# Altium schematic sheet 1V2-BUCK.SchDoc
size A2; SheetNumber: 5; SheetTotal: 17
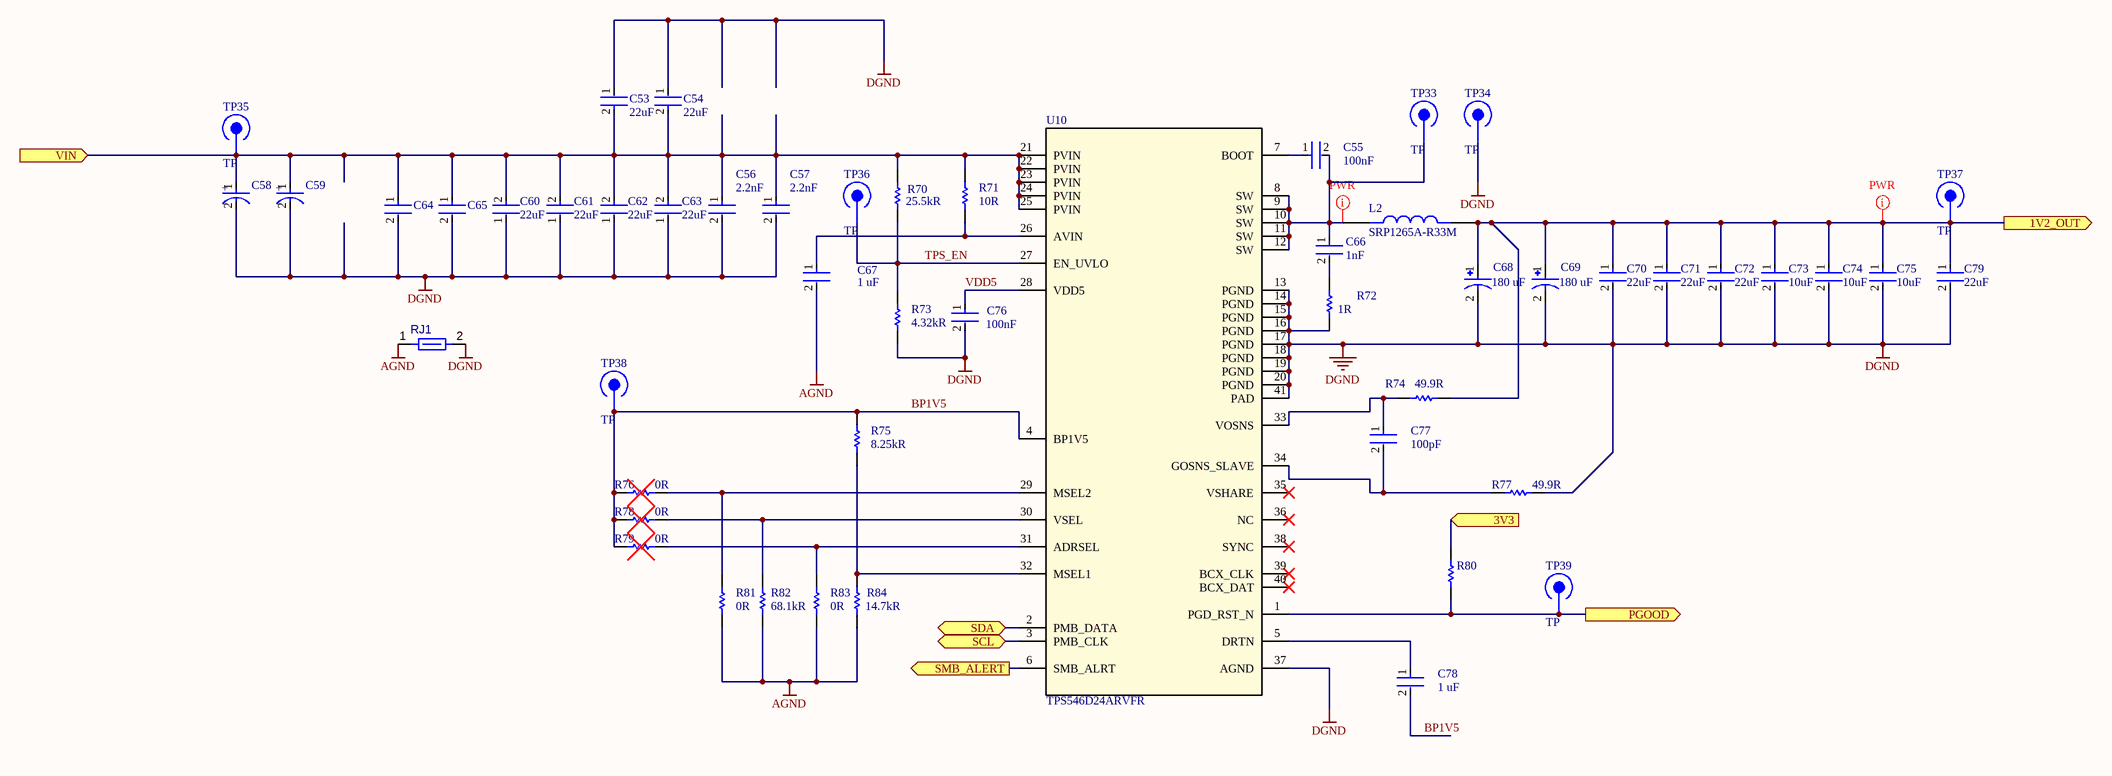
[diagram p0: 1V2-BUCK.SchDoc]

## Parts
C53  Capacitance: 22uF  [FP-GRM31C-0_3-e0_3_0_8-MFG]  (hidden comment: GRM31CC81E226ME11L)
C54  Capacitance: 22uF  [FP-GRM31C-0_3-e0_3_0_8-MFG]  (hidden comment: GRM31CC81E226ME11L)
C55  value 100nF  [FP-CC0402-IPC_B]  (hidden comment: CC0402KRX7R9BB104)
C56  value 2.2nF  [FP-CC0402-MFG]  (hidden comment: CC0402KRX7R8BB222)
C57  value 2.2nF  [FP-CC0402-MFG]  (hidden comment: CC0402KRX7R8BB222)
C58  593D107X9020E2TE3  [593D107X9020E2TE3-Footprint-1]  (value not drawn)
C59  593D107X9020E2TE3  [593D107X9020E2TE3-Footprint-1]  (value not drawn)
C60  Capacitance: 22uF  [FP-GRM31C-0_3-e0_3_0_8-MFG]  (hidden comment: GRM31CC81E226ME11L)
C61  Capacitance: 22uF  [FP-GRM31C-0_3-e0_3_0_8-MFG]  (hidden comment: GRM31CC81E226ME11L)
C62  Capacitance: 22uF  [FP-GRM31C-0_3-e0_3_0_8-MFG]  (hidden comment: GRM31CC81E226ME11L)
C63  Capacitance: 22uF  [FP-GRM31C-0_3-e0_3_0_8-MFG]  (hidden comment: GRM31CC81E226ME11L)
C64  C3216X5R1E476M160AC  [FP-C3216-160-0_2-MFG]  (value not drawn)
C65  C3216X5R1E476M160AC  [FP-C3216-160-0_2-MFG]  (value not drawn)
C66  value 1nF  [FP-CC0805-0_85-MFG]  (hidden comment: CC0805KRX7R9BB102)
C67  value 1 uF  [FP-CC0402-MFG]  (hidden comment: CC0402KRX5R6BB105)
C68  value 180 uF  [EEF-SX0J181ER-Footprint-1]  (hidden comment: EEF-SX0J181ER)
C69  value 180 uF  [EEF-SX0J181ER-Footprint-1]  (hidden comment: EEF-SX0J181ER)
C70  value 22uF  [FP-GRM21B-0_2-e0_2_0_7-MFG]  (hidden comment: GRM21BZ70J226ME44L)
C71  value 22uF  [FP-GRM21B-0_2-e0_2_0_7-MFG]  (hidden comment: GRM21BZ70J226ME44L)
C72  value 22uF  [FP-GRM21B-0_2-e0_2_0_7-MFG]  (hidden comment: GRM21BZ70J226ME44L)
C73  value 10uF  [FP-GRM21B-0_15-MFG]  (hidden comment: GRM21BR71A106KA73L)
C74  value 10uF  [FP-GRM21B-0_15-MFG]  (hidden comment: GRM21BR71A106KA73L)
C75  value 10uF  [FP-GRM21B-0_15-MFG]  (hidden comment: GRM21BR71A106KA73L)
C76  value 100nF  [FP-CC0402-IPC_B]  (hidden comment: CC0402KRX7R9BB104)
C77  value 100pF  [FP-CC0402-MFG]  (hidden comment: CC0402KRX7R9BB101)
C78  value 1 uF  [FP-CC0402-MFG]  (hidden comment: CC0402KRX5R6BB105)
C79  value 22uF  [FP-GRM21B-0_2-e0_2_0_7-MFG]  (hidden comment: GRM21BZ70J226ME44L)
L2  SRP1265A-R33M  [SRP1265A-R33M]
R70  value 25.5kR  [RESC1005X40X25LL10T10]  (hidden comment: RK73H1ETTP2552F)
R71  value 10R  [RESC1005X40X25LL10T10]  (hidden comment: RK73H1ETTP10R0F)
R72  value 1R  [FP-RK73H2E-MFG]  (hidden comment: RK73H2ETTD1R00F)
R73  value 4.32kR  [RESC1005X40X25ML10T10]  (hidden comment: RK73H1ETTP4321F)
R74  value 49.9R  [RESC1005X40X25LL10T10]  (hidden comment: RK73H1ETTP49R9F)
R75  value 8.25kR  [RESC1005X40X25NL10T10]  (hidden comment: RK73H1ETTP8251F)
R76  value 0R  [FP-RK73Z1E-IPC_B]  (hidden comment: RK73Z1ETTP)  (no BOM)
R77  value 49.9R  [RESC1005X40X25LL10T10]  (hidden comment: RK73H1ETTP49R9F)
R78  value 0R  [FP-RK73Z1E-IPC_B]  (hidden comment: RK73Z1ETTP)  (no BOM)
R79  value 0R  [FP-RK73Z1E-IPC_B]  (hidden comment: RK73Z1ETTP)  (no BOM)
R80  RK73H1ETTP1002F  [RESC1005X40X25LL10T10]  (value not drawn)
R81  value 0R  [FP-RK73Z1E-IPC_B]  (hidden comment: RK73Z1ETTP)
R82  value 68.1kR  [RESC1005X40X25LL10T10]  (hidden comment: RK73H1ETTP6812F)
R83  value 0R  [FP-RK73Z1E-IPC_B]  (hidden comment: RK73Z1ETTP)  (no BOM)
R84  value 14.7kR  [RESC1005X40X25LL10T10]  (hidden comment: RK73H1ETTP1472F)
RJ1  Net Tie 12x8mil  [SHORT06-FP]  (value not drawn)  (net tie, no BOM)
TP33  TP  [TP-Footprint-1]
TP34  TP  [TP-Footprint-1]
TP35  TP  [TP-Footprint-1]
TP36  TP  [TP-Footprint-1]
TP37  TP  [TP-Footprint-1]
TP38  TP  [TP-Footprint-1]
TP39  TP  [TP-Footprint-1]
U10  TPS546D24ARVFR  [TPS546D24ARVFR-Footprint-1]

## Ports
1V2_OUT (out), 3V3 (in), PGOOD (out), SCL (bidir), SDA (bidir), SMB_ALERT (out), VIN (in)

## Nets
AGND: C67.2 R81.1 R82.1 R83.1 R84.1 RJ1.1
DGND: C53.1 C54.1 C56.2 C57.2 C58.2(C) C59.2(C) C60.1 C61.1 C62.1 C63.1 C64.2 C65.2 C68.2 C69.2 C70.2 C71.2 C72.2 C73.2 C74.2 C75.2 C76.2 C79.2 R72.1 R73.1 R77.2 RJ1.2 TP34.1 U10.13(PGND) U10.14(PGND) U10.15(PGND) U10.16(PGND) U10.17(PGND) U10.18(PGND) U10.19(PGND) U10.20(PGND) U10.37(AGND) U10.41(PAD)
1V2_OUT: C68.1 C69.1 C70.1 C71.1 C72.1 C73.1 C74.1 C75.1 C79.1 L2.2 R74.2 TP37.1 ; port 1V2_OUT
3V3: R80.2 ; port 3V3
BP1V5: C78.2 R75.1 R76.2 R78.2 R79.2 TP38.1 U10.4(BP1V5)
PGOOD: R80.1 TP39.1 U10.1(PGD_RST_N) ; port PGOOD
SCL: U10.3(PMB_CLK) ; port SCL
SDA: U10.2(PMB_DATA) ; port SDA
SMB_ALERT: U10.6(SMB_ALRT) ; port SMB_ALERT
TPS_EN: R70.1 R73.2 TP36.1 U10.27(EN_UVLO)
VDD5: C76.1 U10.28(VDD5)
VIN: C53.2 C54.2 C56.1 C57.1 C58.1(A) C59.1(A) C60.2 C61.2 C62.2 C63.2 C64.1 C65.1 R70.2 R71.2 TP35.1 U10.21(PVIN) U10.22(PVIN) U10.23(PVIN) U10.24(PVIN) U10.25(PVIN) ; port VIN
NetC55_1: C55.1 U10.7(BOOT)
NetC55_2: C55.2 C66.1 L2.1 TP33.1 U10.8(SW) U10.9(SW) U10.10(SW) U10.11(SW) U10.12(SW)
NetC66_2: C66.2 R72.2
NetC67_1: C67.1 R71.1 U10.26(AVIN)
NetC77_1: C77.1 R74.1 U10.33(VOSNS)
NetC77_2: C77.2 R77.1 U10.34(GOSNS_SLAVE)
NetC78_1: C78.1 U10.5(DRTN)
NetR75_2: R75.2 R84.2 U10.32(MSEL1)
NetR76_1: R76.1 R81.2 U10.29(MSEL2)
NetR78_1: R78.1 R82.2 U10.30(VSEL)
NetR79_1: R79.1 R83.2 U10.31(ADRSEL)

Not connected (* = marked no-connect by the designer): U10 35(VSHARE)* 36(NC)* 38(SYNC)* 39(BCX_CLK)* 40(BCX_DAT)*

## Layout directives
net class PWR: 1V2_OUT, NetC55_2

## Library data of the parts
C53 C54 C60-C63 = CMP-06035-043516-1: Chip Multilayer Ceramic Capacitors for General Purpose, 1206, 22uF, X6S, 22%, 20%, 25V
C55 C76 = CMP-x00152-1: Ceramic Capacitor, Multilayer, Ceramic, 50V, 10% +Tol, 10% -Tol, X7R, 15% TC, 0.1uF, Surface Mount, 0402
C56 C57 = CMP-x00156-1: Ceramic Capacitor, Multilayer, Ceramic, 25V, 10% +Tol, 10% -Tol, X7R, 15% TC, 0.0022uF, Surface Mount, 0402
C58 C59 = CMP-001-00321-3: No Description Available; Mfr_Name: Vishay
C64 C65 = CMP-2000-05397-3: Multilayer Ceramic Capacitors 47uF ±20% 25V X5R SMD 1206
C66 = CMP-x00143-1: Ceramic Capacitor, Multilayer, Ceramic, 50V, 10% +Tol, 10% -Tol, X7R, 15% TC, 0.001uF, Surface Mount, 0805
C67 C78 = CMP-03422-000489-1: CAP CER 1UF 10V X5R 0402; Manufacturer: YAGEO; Temperature Coefficient: 30ppm/°C; Tolerance: 0.1; Automotive Grade: NA; Material: Ceramic
C68 C69 = CMP-x00146-3: Cap Aluminum Polymer 180uF 6.3VDC 20%( 7.3 X 4.3 X 1.9mm) SMD 0.009 Ohm 6300mA 2000h 105C T/R; Manufacturer: Panasonic; Vendor: TTI; Template: PS_SMD2_C; Reel Width: 12mm
C70-C72 C79 = CMP-x00148-1: Ceramic Capacitor, Multilayer, Ceramic, 6.3V, 20% +Tol, 20% -Tol, X7R, 15% TC, 22uF, Surface Mount, 0805
C73-C75 = CMP-x00157-1: Ceramic Capacitor, Multilayer, Ceramic, 10V, 10% +Tol, 10% -Tol, X7R, 15% TC, 10uF, Surface Mount, 0805
C77 = CMP-x00153-1: Ceramic Capacitor, Multilayer, Ceramic, 50V, 10% +Tol, 10% -Tol, X7R, 15% TC, 0.0001uF, Surface Mount, 0402
L2 = CMP-00047-01-A-1: General Purpose Inductor, 0.33uH, 20%, 1 Element, Carbonyl Powder-Core, SMD, 5349; Quality Factor-Min (at L-nom): 10; Package Length: 13.5mm; Channels: 1; Package Height: 6.2mm; Shape/Size Description: RECTANGULAR PACKAGE; Reference Standard: AEC-Q200; DC Resistance (DCR): 0.8mR; Inductor Application: POWER INDUCTOR; Max Current Rating: 46A; Case/Size Code: 5349; Shielding: Shielded; Package Width: 12.5mm; Self Resonant Frequency: 90MHz; Test Frequency: 100kHz
R70 = CMP-x00151-1: BOM UPDATE 25.5K (NEW) RESISTOR FROM 11.7K (OLD) / NEW: RK73H1ETTP2552F
R71 = CMP-x00144-1: Fixed Resistor, Metal Glaze/thick Film, 0.1W, 10ohm, 75V, 1% +/-Tol, 100ppm/Cel, Surface Mount, 0402
R72 = CMP-x00142-1: Fixed Resistor, Metal Glaze/thick Film, 0.5W, 1ohm, 200V, 1% +/-Tol, 200ppm/Cel, Surface Mount, 1210; Manufacturer: KOA Speer; Template: KO_0402; Reel Width: 8mm; Vendor: TTI
R73 = CMP-2002-04015-1: BOM UPDATE 4.32K (NEW) RESISTOR FROM 37.4K (OLD) / NEW: RK73H1ETTP4321F; Manufacturer: KOA Speer; Part Number: RK73H1ETTP3741F
R74 R77 = CMP-x00154-1: Fixed Resistor, Metal Glaze/thick Film, 0.1W, 49.9ohm, 75V, 1% +/-Tol, 100ppm/Cel, Surface Mount, 0402
R75 = CMP-2002-04539-1: Manufacturer: KOA Speer
R76 R78 R79 R81 R83 = CMP-x00147-1: Metal Glaze/thick Film, 0ohm, Surface Mount, 0402
R80 = CMP-x00150-1: Fixed Resistor, Metal Glaze/thick Film, 0.1W, 10000ohm, 75V, 1% +/-Tol, 100ppm/Cel, Surface Mount, 0402; Value: 10kR
R82 = CMP-x00145-1: Fixed Resistor, Metal Glaze/thick Film, 0.1W, 68100ohm, 75V, 1% +/-Tol, 100ppm/Cel, Surface Mount, 0402
R84 = CMP-x00149-1: Fixed Resistor, Metal Glaze/thick Film, 0.1W, 14700ohm, 75V, 1% +/-Tol, 100ppm/Cel, Surface Mount, 0402
RJ1 = CMP-009-00121-2
TP33-TP39 = CMP-001-0086-3: digital shovel test point
U10 = CMP-x00141-6: Switching Regulator, Current-mode, 40A, 1500kHz Switching Freq-Max, PQCC40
